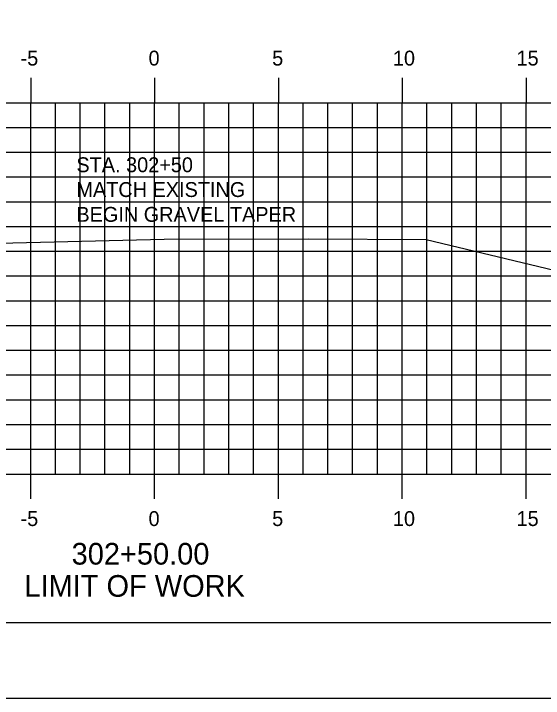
# Model space of a CAD drawing. Extents: x 1136767 to 1136937, y 608981 to 609091.
# Drawn here: x 1136844.7 to 1136866.08, y 608981.28 to 609008.93 of the extents above; entities that cross this region are included whole.
import ezdxf

# ---------------------------------------------------------------- set-up
doc = ezdxf.new("R2010")
doc.units = 0
for name, color, linetype in [('ANNOTATION', 7, 'Continuous'), ('BORDER', 7, 'Continuous'), ('H_V ANNOTATION', 7, 'Continuous'), ('MAJOR', 7, 'Continuous'), ('MINOR', 7, 'Continuous'), ('PLOT BOUNDARY', 7, 'Continuous'), ('S_Roadway_Centerline', 7, 'Continuous')]:
    doc.layers.add(name, color=color, linetype=linetype)

msp = doc.modelspace()

# ---------------------------------------------------------------- linework, layer by layer
at = {"layer": 'BORDER'}
msp.add_lwpolyline([(1136775.383, 608984.335), (1136935.383, 608984.335), (1136935.383, 609089.335), (1136775.383, 609089.335)], close=True, dxfattribs=at)
at = {"layer": 'MAJOR'}
for p, q in [((1136845.383, 609006.337), (1136845.383, 609005.335)), ((1136850.383, 609006.337), (1136850.383, 609005.335)), ((1136855.383, 609006.337), (1136855.383, 609005.335)), ((1136860.383, 609006.337), (1136860.383, 609005.335)), ((1136865.383, 609006.337), (1136865.383, 609005.335)), ((1136780.383, 609005.335), (1136920.383, 609005.335)), ((1136780.383, 609005.335), (1136920.383, 609005.335)), ((1136845.383, 608990.335), (1136845.383, 609005.335)), ((1136850.383, 608990.335), (1136850.383, 609005.335)), ((1136855.383, 608990.335), (1136855.383, 609005.335)), ((1136860.383, 608990.335), (1136860.383, 609005.335)), ((1136865.383, 608990.335), (1136865.383, 609005.335)), ((1136780.383, 609000.335), (1136920.383, 609000.335)), ((1136780.383, 608995.335), (1136920.383, 608995.335)), ((1136780.383, 608990.335), (1136920.383, 608990.335)), ((1136780.383, 608990.335), (1136920.383, 608990.335)), ((1136845.383, 608989.333), (1136845.383, 608990.335)), ((1136850.383, 608989.333), (1136850.383, 608990.335)), ((1136855.383, 608989.333), (1136855.383, 608990.335)), ((1136860.383, 608989.333), (1136860.383, 608990.335)), ((1136865.383, 608989.333), (1136865.383, 608990.335))]:
    msp.add_line(p, q, dxfattribs=at)
at = {"layer": 'MINOR'}
for p, q in [((1136846.383, 608990.335), (1136846.383, 609005.335)), ((1136847.383, 608990.335), (1136847.383, 609005.335)), ((1136848.383, 608990.335), (1136848.383, 609005.335)), ((1136849.383, 608990.335), (1136849.383, 609005.335)), ((1136851.383, 608990.335), (1136851.383, 609005.335)), ((1136852.383, 608990.335), (1136852.383, 609005.335)), ((1136853.383, 608990.335), (1136853.383, 609005.335)), ((1136854.383, 608990.335), (1136854.383, 609005.335)), ((1136856.383, 608990.335), (1136856.383, 609005.335)), ((1136857.383, 608990.335), (1136857.383, 609005.335)), ((1136858.383, 608990.335), (1136858.383, 609005.335)), ((1136859.383, 608990.335), (1136859.383, 609005.335)), ((1136861.383, 608990.335), (1136861.383, 609005.335)), ((1136862.383, 608990.335), (1136862.383, 609005.335)), ((1136863.383, 608990.335), (1136863.383, 609005.335)), ((1136864.383, 608990.335), (1136864.383, 609005.335)), ((1136780.383, 609004.335), (1136920.383, 609004.335)), ((1136780.383, 609003.335), (1136920.383, 609003.335)), ((1136780.383, 609002.335), (1136920.383, 609002.335)), ((1136780.383, 609001.335), (1136920.383, 609001.335)), ((1136780.383, 608999.335), (1136920.383, 608999.335)), ((1136780.383, 608998.335), (1136920.383, 608998.335)), ((1136780.383, 608997.335), (1136920.383, 608997.335)), ((1136780.383, 608996.335), (1136920.383, 608996.335)), ((1136780.383, 608994.335), (1136920.383, 608994.335)), ((1136780.383, 608993.335), (1136920.383, 608993.335)), ((1136780.383, 608992.335), (1136920.383, 608992.335)), ((1136780.383, 608991.335), (1136920.383, 608991.335))]:
    msp.add_line(p, q, dxfattribs=at)
at = {"layer": 'PLOT BOUNDARY'}
msp.add_lwpolyline([(1136767.29, 608981.276), (1136937.29, 608981.276), (1136937.29, 609091.276), (1136767.29, 609091.276)], close=True, dxfattribs=at)
at = {"layer": 'S_Roadway_Centerline'}
msp.add_lwpolyline([(1136819.07, 608999.229), (1136827.733, 608999.346), (1136831.155, 608999.469), (1136836.465, 608999.354), (1136837.328, 608999.415), (1136838.592, 608999.439), (1136839.398, 608999.507), (1136844.656, 608999.671), (1136850.774, 608999.819), (1136856.604, 608999.836), (1136861.347, 608999.808), (1136867.818, 608998.265), (1136870.243, 608997.662), (1136877.713, 608999.351), (1136881.339, 609000.131), (1136890.461, 609000.106), (1136896.884, 609000.009), (1136898.771, 608999.999), (1136909.82, 609000.138), (1136917.953, 609000.183), (1136919.115, 609000.153), (1136920.383, 609000.132)], dxfattribs=at)

# ---------------------------------------------------------------- texts
at = {"layer": 'ANNOTATION'}
for s, p in [('STA. 302+50', (1136847.228, 609002.527)), ('MATCH EXISTING', (1136847.228, 609001.525)), ('BEGIN GRAVEL TAPER', (1136847.228, 609000.523))]:
    msp.add_text(s, height=0.6, dxfattribs=at).set_placement(p)
at = {"layer": 'H_V ANNOTATION'}
for s, height, p in [('-5', 0.6, (1136844.974, 609006.835)), ('0', 0.6, (1136850.142, 609006.835)), ('5', 0.6, (1136855.134, 609006.835)), ('10', 0.6, (1136860.009, 609006.835)), ('15', 0.6, (1136865.001, 609006.835)), ('-5', 0.6, (1136844.974, 608988.235)), ('0', 0.6, (1136850.142, 608988.235)), ('5', 0.6, (1136855.134, 608988.235)), ('10', 0.6, (1136860.009, 608988.235)), ('15', 0.6, (1136865.001, 608988.235)), ('302+50.00', 0.875, (1136847.036, 608986.677)), ('LIMIT OF WORK', 0.87498, (1136845.129, 608985.378))]:
    msp.add_text(s, height=height, dxfattribs=at).set_placement(p)
at = {"layer": 'S_Roadway_Centerline'}
for s, p in [('C', (1136850.769, 608999.819)), ('L', (1136850.774, 608999.811))]:
    msp.add_text(s, height=0.0146, dxfattribs=at).set_placement(p)

doc.saveas('drawing.dxf')
